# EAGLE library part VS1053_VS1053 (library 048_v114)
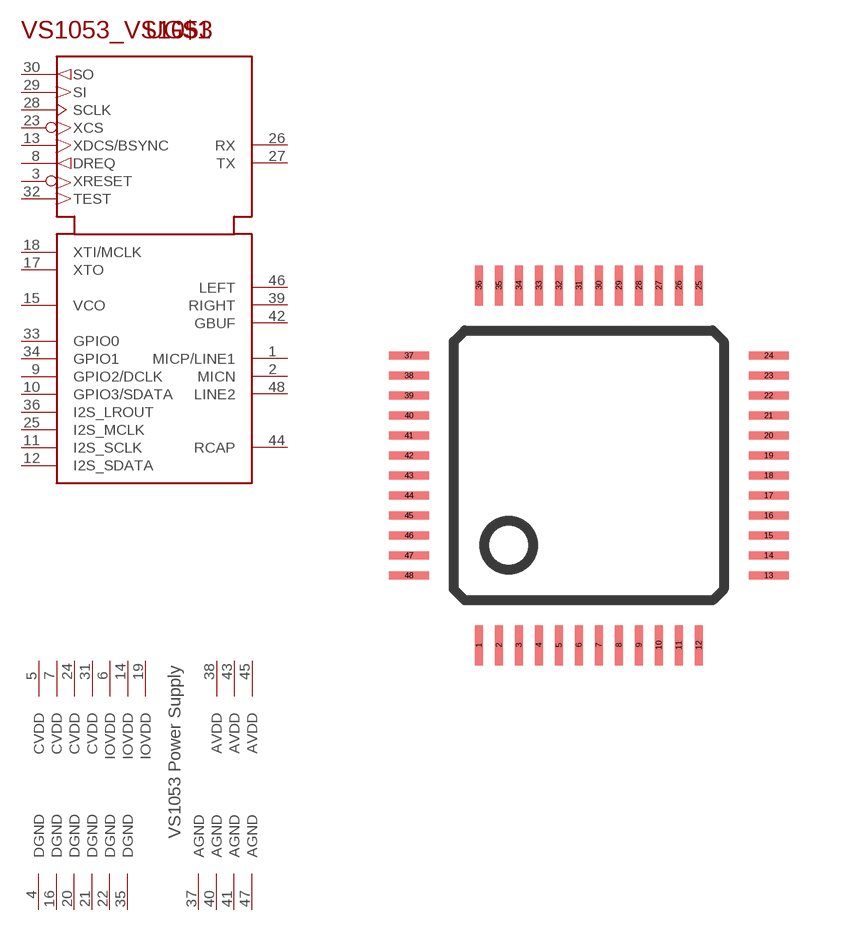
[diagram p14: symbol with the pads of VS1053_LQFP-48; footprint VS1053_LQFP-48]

Designator prefix -; gates G$1=VS1053_VS1053 G$2=VS1053_POWER

## VS1053_VS1053  [VS1053_LQFP-48]
1  G$1:MICP/LINE1  in
2  G$1:MICN
3  G$1:XRESET  in
4  G$2:DGND  pwr
5  G$2:CVDD  pwr
6  G$2:IOVDD  pwr
7  G$2:CVDD  pwr
8  G$1:DREQ  out
9  G$1:GPIO2/DCLK
10  G$1:GPIO3/SDATA
11  G$1:I2S_SCLK
12  G$1:I2S_SDATA
13  G$1:XDCS/BSYNC
14  G$2:IOVDD  pwr
15  G$1:VCO  out
16  G$2:DGND  pwr
17  G$1:XTO  out
18  G$1:XTI/MCLK  in
19  G$2:IOVDD  pwr
20  G$2:DGND  pwr
21  G$2:DGND  pwr
22  G$2:DGND  pwr
23  G$1:XCS  in
24  G$2:CVDD  pwr
25  G$1:I2S_MCLK
26  G$1:RX  in
27  G$1:TX
28  G$1:SCLK  in
29  G$1:SI  in
30  G$1:SO  out
31  G$2:CVDD  pwr
32  G$1:TEST  in
33  G$1:GPIO0
34  G$1:GPIO1
35  G$2:DGND  pwr
36  G$1:I2S_LROUT
37  G$2:AGND  pwr
38  G$2:AVDD  pwr
39  G$1:RIGHT  out
40  G$2:AGND  pwr
41  G$2:AGND  pwr
42  G$1:GBUF  out
43  G$2:AVDD  pwr
44  G$1:RCAP  in
45  G$2:AVDD  pwr
46  G$1:LEFT  out
47  G$2:AGND  pwr
48  G$1:LINE2  in

## Footprint VS1053_LQFP-48 (pad centres in mm)
smd 0.2 x 1: 1 -2.75,-4.5; 2 -2.25,-4.5; 3 -1.75,-4.5; 4 -1.25,-4.5; 5 -0.75,-4.5; 6 -0.25,-4.5; 7 0.25,-4.5; 8 0.75,-4.5; 9 1.25,-4.5; 10 1.75,-4.5; 11 2.25,-4.5; 12 2.75,-4.5; 25 2.75,4.5; 26 2.25,4.5; 27 1.75,4.5; 28 1.25,4.5; 29 0.75,4.5; 30 0.25,4.5; 31 -0.25,4.5; 32 -0.75,4.5; 33 -1.25,4.5; 34 -1.75,4.5; 35 -2.25,4.5; 36 -2.75,4.5
smd 1 x 0.2: 13 4.5,-2.75; 14 4.5,-2.25; 15 4.5,-1.75; 16 4.5,-1.25; 17 4.5,-0.75; 18 4.5,-0.25; 19 4.5,0.25; 20 4.5,0.75; 21 4.5,1.25; 22 4.5,1.75; 23 4.5,2.25; 24 4.5,2.75; 37 -4.5,2.75; 38 -4.5,2.25; 39 -4.5,1.75; 40 -4.5,1.25; 41 -4.5,0.75; 42 -4.5,0.25; 43 -4.5,-0.25; 44 -4.5,-0.75; 45 -4.5,-1.25; 46 -4.5,-1.75; 47 -4.5,-2.25; 48 -4.5,-2.75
